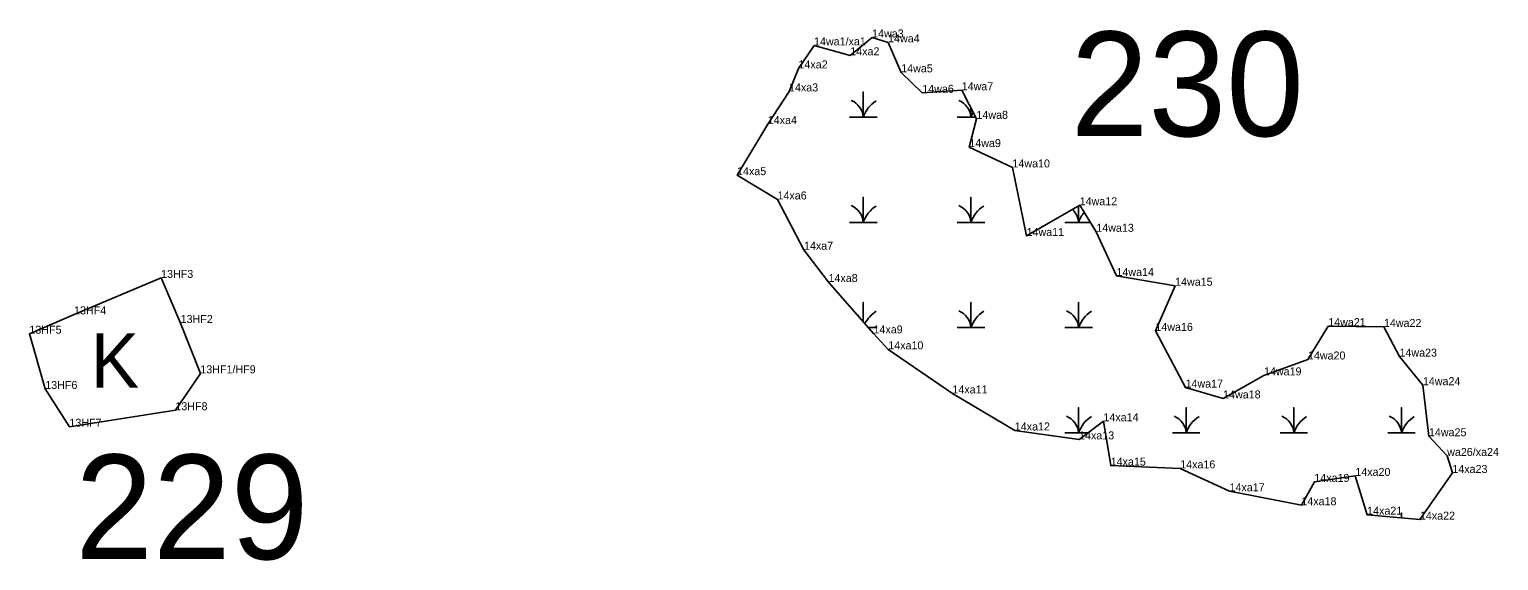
# Model space of a CAD drawing. Extents: x 2072529 to 2268796, y 436423 to 470406.
# Drawn here: x 2251631 to 2252549, y 444274 to 444607 of the extents above; entities that cross this region are included whole.
import ezdxf

# ---------------------------------------------------------------- set-up
doc = ezdxf.new("R2010")
doc.units = 0
for name, color, linetype in [('Default', 7, 'Continuous'), ('Exist Environmental Wetland Boundary', 7, 'Continuous'), ('Exist Environmental Wetland Boundary Cogo Comment', 7, 'Continuous'), ('Exist Hydro Swamp or Marsh', 7, 'Continuous'), ('Old_Level_20', 7, 'Continuous')]:
    doc.layers.add(name, color=color, linetype=linetype)

msp = doc.modelspace()

# ---------------------------------------------------------------- linework, layer by layer
at = {"layer": 'Exist Environmental Wetland Boundary'}
for points in [[(2252120.98, 444596.54), (2252111.24, 444582.13), (2252105.34, 444567.74), (2252092.07, 444547.33), (2252072.87, 444515.38), (2252098.14, 444500.19), (2252114.68, 444468.74), (2252130, 444448.56), (2252158.12, 444416.44), (2252167.36, 444406.46), (2252207.43, 444378.88), (2252246.42, 444355.74), (2252286.59, 444350.14), (2252301.81, 444361.49), (2252306.34, 444333.76), (2252349.78, 444332.03), (2252380.59, 444317.71), (2252425.49, 444308.98), (2252433.6, 444323.56), (2252459.2, 444327.32), (2252466.58, 444303.07), (2252499.57, 444299.98), (2252519.83, 444329.15), (2252516.59, 444339.79), (2252505.2, 444352.12), (2252501.41, 444384.06), (2252486.79, 444401.91), (2252477.08, 444420.46), (2252442.28, 444420.99), (2252429.61, 444400.12), (2252402.13, 444390.19), (2252376.6, 444375.77), (2252353.11, 444382.55), (2252334.27, 444418.02), (2252346.6, 444446.23), (2252309.95, 444452.34), (2252297.36, 444479.97), (2252286.96, 444496.54), (2252253.79, 444477.34), (2252244.95, 444520.22), (2252218, 444532.96), (2252222.45, 444550.6), (2252213.24, 444568.46), (2252188.62, 444566.86), (2252175.44, 444579.67), (2252167.26, 444598.42), (2252157.26, 444601.48), (2252143.61, 444590.31)], [(2251737.5, 444391.44), (2251725.18, 444422.92), (2251712.98, 444451.12), (2251658.59, 444428.35), (2251630.67, 444416.25), (2251640.6, 444381.68), (2251655.69, 444358.09), (2251721.9, 444368.39)]]:
    msp.add_lwpolyline(points, close=True, dxfattribs=at)
at = {"layer": 'Exist Hydro Swamp or Marsh'}
for points in [[(2252143.17, 444551.63), (2252151.77, 444551.63), (2252151.77, 444567.41), (2252151.77, 444551.63), (2252160.37, 444551.63)], [(2252210.42, 444551.63), (2252219.02, 444551.63), (2252219.02, 444557.26)], [(2252219.02, 444557.26), (2252219.02, 444551.63), (2252221.92, 444551.63)], [(2252143.17, 444485.83), (2252151.77, 444485.83), (2252151.77, 444501.61), (2252151.77, 444485.83), (2252160.37, 444485.83)], [(2252210.42, 444485.83), (2252219.02, 444485.83), (2252219.02, 444501.61), (2252219.02, 444485.83), (2252227.62, 444485.83)], [(2252277.67, 444485.83), (2252286.27, 444485.83), (2252286.27, 444496.14)], [(2252286.27, 444496.14), (2252286.27, 444485.83), (2252293.68, 444485.83)], [(2252151.77, 444423.69), (2252151.77, 444435.81), (2252151.77, 444423.69)], [(2252210.42, 444420.03), (2252219.02, 444420.03), (2252219.02, 444435.81), (2252219.02, 444420.03), (2252227.62, 444420.03)], [(2252277.67, 444420.03), (2252286.27, 444420.03), (2252286.27, 444435.81), (2252286.27, 444420.03), (2252294.87, 444420.03)], [(2252154.97, 444420.03), (2252160.37, 444420.03)], [(2252277.67, 444354.23), (2252286.27, 444354.23), (2252286.27, 444370.01), (2252286.27, 444354.23), (2252292.08, 444354.23)], [(2252344.92, 444354.23), (2252353.52, 444354.23), (2252353.52, 444370.01), (2252353.52, 444354.23), (2252362.12, 444354.23)], [(2252412.17, 444354.23), (2252420.77, 444354.23), (2252420.77, 444370.01), (2252420.77, 444354.23), (2252429.37, 444354.23)], [(2252479.42, 444354.23), (2252488.02, 444354.23), (2252488.02, 444370.01), (2252488.02, 444354.23), (2252496.62, 444354.23)], [(2252488.02, 444301.06), (2252488.02, 444304.21), (2252488.02, 444301.06)]]:
    msp.add_lwpolyline(points, dxfattribs=at)
for centre, radius, start, end in [((2252139.5, 444550.75), 12.3, 4.14034, 67.53497), ((2252170.01, 444545.57), 19.22, 122.12745, 161.62219), ((2252206.75, 444550.75), 12.3, 4.14034, 67.53497), ((2252237.26, 444545.57), 19.22, 151.6693, 161.62219), ((2252139.5, 444484.95), 12.3, 4.14034, 67.53497), ((2252170.01, 444479.77), 19.22, 122.12745, 161.62219), ((2252206.75, 444484.95), 12.3, 4.14034, 67.53497), ((2252237.26, 444479.77), 19.22, 122.12745, 161.62219), ((2252274, 444484.95), 12.3, 4.14034, 46.80057), ((2252304.51, 444479.77), 19.22, 140.14803, 161.62219), ((2252139.5, 444419.15), 12.3, 34.91826, 47.4844), ((2252170.01, 444413.97), 19.22, 122.12745, 153.59387), ((2252206.75, 444419.15), 12.3, 4.14034, 67.53497), ((2252237.26, 444413.97), 19.22, 122.12745, 161.62219), ((2252274, 444419.15), 12.3, 4.14034, 67.53497), ((2252304.51, 444413.97), 19.22, 122.12745, 161.62219), ((2252274, 444353.35), 12.3, 4.14034, 67.53497), ((2252304.51, 444348.17), 19.22, 122.12745, 161.62219), ((2252341.25, 444353.35), 12.3, 4.14034, 67.53497), ((2252371.76, 444348.17), 19.22, 122.12745, 161.62219), ((2252408.5, 444353.35), 12.3, 4.14034, 67.53497), ((2252439.01, 444348.17), 19.22, 122.12745, 161.62219), ((2252475.75, 444353.35), 12.3, 4.14034, 67.53497), ((2252506.26, 444348.17), 19.22, 122.12745, 161.62219)]:
    msp.add_arc(centre, radius, start, end, dxfattribs=at)
at = {"layer": 'Old_Level_20'}
for p, q in [((2252157.26, 444601.48), (2252157.26, 444601.48)), ((2252120.98, 444596.54), (2252120.98, 444596.54)), ((2252167.26, 444598.42), (2252167.26, 444598.42)), ((2252143.61, 444590.31), (2252143.61, 444590.31)), ((2252111.24, 444582.13), (2252111.24, 444582.13)), ((2252175.44, 444579.67), (2252175.44, 444579.67)), ((2252105.34, 444567.74), (2252105.34, 444567.74)), ((2252188.62, 444566.86), (2252188.62, 444566.86)), ((2252213.24, 444568.46), (2252213.24, 444568.46)), ((2252092.07, 444547.33), (2252092.07, 444547.33)), ((2252222.45, 444550.6), (2252222.45, 444550.6)), ((2252218, 444532.96), (2252218, 444532.96)), ((2252244.95, 444520.22), (2252244.95, 444520.22)), ((2252072.87, 444515.38), (2252072.87, 444515.38)), ((2252098.14, 444500.19), (2252098.14, 444500.19)), ((2252286.96, 444496.54), (2252286.96, 444496.54)), ((2252253.79, 444477.34), (2252253.79, 444477.34)), ((2252297.36, 444479.97), (2252297.36, 444479.97)), ((2252114.68, 444468.74), (2252114.68, 444468.74)), ((2251712.98, 444451.12), (2251712.98, 444451.12)), ((2252130, 444448.56), (2252130, 444448.56)), ((2252309.95, 444452.34), (2252309.95, 444452.34)), ((2252346.6, 444446.23), (2252346.6, 444446.23)), ((2251658.59, 444428.35), (2251658.59, 444428.35)), ((2251725.18, 444422.92), (2251725.18, 444422.92)), ((2252334.27, 444418.02), (2252334.27, 444418.02)), ((2252442.28, 444420.99), (2252442.28, 444420.99)), ((2252477.08, 444420.46), (2252477.08, 444420.46)), ((2251630.67, 444416.25), (2251630.67, 444416.25)), ((2252158.12, 444416.44), (2252158.12, 444416.44)), ((2252167.36, 444406.46), (2252167.36, 444406.46)), ((2252429.61, 444400.12), (2252429.61, 444400.12)), ((2252486.79, 444401.91), (2252486.79, 444401.91)), ((2251737.5, 444391.44), (2251737.5, 444391.44)), ((2252402.13, 444390.19), (2252402.13, 444390.19)), ((2251640.6, 444381.68), (2251640.6, 444381.68)), ((2252353.11, 444382.55), (2252353.11, 444382.55)), ((2252501.41, 444384.06), (2252501.41, 444384.06)), ((2252207.43, 444378.88), (2252207.43, 444378.88)), ((2252376.6, 444375.77), (2252376.6, 444375.77)), ((2251721.9, 444368.39), (2251721.9, 444368.39)), ((2251655.69, 444358.09), (2251655.69, 444358.09)), ((2252246.42, 444355.74), (2252246.42, 444355.74)), ((2252301.81, 444361.49), (2252301.81, 444361.49)), ((2252286.59, 444350.14), (2252286.59, 444350.14)), ((2252505.2, 444352.12), (2252505.2, 444352.12)), ((2252516.59, 444339.79), (2252516.59, 444339.79)), ((2252306.34, 444333.76), (2252306.34, 444333.76)), ((2252349.78, 444332.03), (2252349.78, 444332.03)), ((2252459.2, 444327.32), (2252459.2, 444327.32)), ((2252519.83, 444329.15), (2252519.83, 444329.15)), ((2252380.59, 444317.71), (2252380.59, 444317.71)), ((2252433.6, 444323.56), (2252433.6, 444323.56)), ((2252425.49, 444308.98), (2252425.49, 444308.98)), ((2252466.58, 444303.07), (2252466.58, 444303.07)), ((2252499.57, 444299.98), (2252499.57, 444299.98))]:
    msp.add_line(p, q, dxfattribs=at)

# ---------------------------------------------------------------- texts
at = {"layer": 'Default'}
for s, p in [('230', (2252281.33, 444539.78)), ('229', (2251659.3, 444275.27))]:
    msp.add_text(s, height=65.34, dxfattribs=at).set_placement(p)
at = {"layer": 'Exist Environmental Wetland Boundary Cogo Comment'}
for s, p in [('14wa1/xa1', (2252120.98, 444596.54)), ('14wa3', (2252157.26, 444601.48)), ('14wa4', (2252167.26, 444598.42)), ('14xa2', (2252143.61, 444590.31)), ('14xa2', (2252111.24, 444582.13)), ('14wa5', (2252175.44, 444579.67)), ('14xa3', (2252105.34, 444567.74)), ('14wa6', (2252188.62, 444566.86)), ('14wa7', (2252213.24, 444568.46)), ('14wa8', (2252222.45, 444550.6)), ('14xa4', (2252092.07, 444547.33)), ('14wa9', (2252218, 444532.96)), ('14xa5', (2252072.87, 444515.38)), ('14wa10', (2252244.95, 444520.22)), ('14xa6', (2252098.14, 444500.19)), ('14wa12', (2252286.96, 444496.54)), ('14wa11', (2252253.79, 444477.34)), ('14wa13', (2252297.36, 444479.97)), ('14xa7', (2252114.68, 444468.74)), ('13HF3', (2251712.98, 444451.12)), ('14wa14', (2252309.95, 444452.34)), ('14xa8', (2252130, 444448.56)), ('14wa15', (2252346.6, 444446.23)), ('13HF4', (2251658.59, 444428.35)), ('13HF2', (2251725.18, 444422.92)), ('13HF5', (2251630.67, 444416.25)), ('14xa9', (2252158.12, 444416.44)), ('14wa16', (2252334.27, 444418.02)), ('14wa21', (2252442.28, 444420.99)), ('14wa22', (2252477.08, 444420.46)), ('14xa10', (2252167.36, 444406.46)), ('14wa20', (2252429.61, 444400.12)), ('14wa23', (2252486.79, 444401.91)), ('13HF1/HF9', (2251737.5, 444391.44)), ('14wa19', (2252402.13, 444390.19)), ('13HF6', (2251640.6, 444381.68)), ('14xa11', (2252207.43, 444378.88)), ('14wa17', (2252353.11, 444382.55)), ('14wa24', (2252501.41, 444384.06)), ('13HF8', (2251721.9, 444368.39)), ('14wa18', (2252376.6, 444375.77)), ('13HF7', (2251655.69, 444358.09)), ('14xa14', (2252301.81, 444361.49)), ('14xa12', (2252246.42, 444355.74)), ('14xa13', (2252286.59, 444350.14)), ('14wa25', (2252505.2, 444352.12)), ('wa26/xa24', (2252516.59, 444339.79)), ('14xa15', (2252306.34, 444333.76)), ('14xa16', (2252349.78, 444332.03)), ('14xa19', (2252433.6, 444323.56)), ('14xa20', (2252459.2, 444327.32)), ('14xa23', (2252519.83, 444329.15)), ('14xa17', (2252380.59, 444317.71)), ('14xa18', (2252425.49, 444308.98)), ('14xa21', (2252466.58, 444303.07)), ('14xa22', (2252499.57, 444299.98))]:
    msp.add_text(s, height=5, dxfattribs=at).set_placement(p)
at = {"layer": 'Exist Hydro Swamp or Marsh'}
msp.add_text('K', height=34, dxfattribs=at).set_placement((2251668.92, 444382.47))

doc.saveas('drawing.dxf')
